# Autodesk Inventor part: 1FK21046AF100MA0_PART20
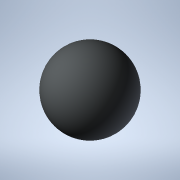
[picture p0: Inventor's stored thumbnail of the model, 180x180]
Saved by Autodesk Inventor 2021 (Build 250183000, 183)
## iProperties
Created: 2025-04
Part Number: 1FK21046AF100MA0_PART20
Material: Generic
Catalog Web Link: www.3dfindit.com
Description: -Servo synchronous motor
Document SubType Name: Modeling
Designer: psAdmin
Mass: 0.137258 g
Surface Area: 1.2868 cm^2
Volume: 0.137258 cm^3
Density: 1 g/cm^3
Appearance: PSOLRGB-212-217-219
Category: PARTsolutions
Title: 1FK21046AF100MA0_PART20
Author: Cadenas PARTsolutions
Comments: Servo synchronous motor
Sending System: PARTsolutions
Preprocessor: ST-DEVELOPER v19.3
PSOL_IDENT_0: {$CADENAS_DATA/23d-libs/siemens_ag/_cat_/4f/2b/1fk21046af100ma0.prj},216 {VTYP=3D},{NB=1FK21046AF100
PSOL_IDENT_1: MA0_PART20},{LINA=1FK21046AF100MA0_PART20},{NN=1FK21046AF100MA0_PART20},{NOPRJ=TRUE},{DATE=19.08.202
PSOL_IDENT_2: 5 14:00:37},{GEOMDATE=30.07.2025 02:01:06},{VERSION=},{LINEID=10},{WBVAR=},{WBNUMERIC=}  {NB=1FK2104
PSOL_IDENT_3: 6AF100MA0_PART20},{LINA=1FK21046AF100MA0_PART20},{KT=DUMMY},{PREVIEW=../../../_pool_/cb/72/p_d211_xx
PSOL_IDENT_4: _00434j.png},{DESCSHORT=SIMOTICS S-1FK2 HD, SINAMICS S210 3AC 400V-480V, 3.2 Nm, 3000 rpm},{DESCLONG=
PSOL_IDENT_5: SIMOTICS S-1FK2 HD servo motor M0=3.2 Nm; PN = 1 kW at nN=3000 rpm (380-480 V); PN = 0.5 kW at nN=15
PSOL_IDENT_6: 00 rpm (200-240 V); with holding brake; degree of protection IP64; cylindrical shaft D19x40mm; absol
PSOL_IDENT_7: ute encoder 22-bit + 12-bit multiturn (encoder AM22DQC); with OCC interface; plug size M17, rotatabl
PSOL_IDENT_8: e; SIMOTICS S-1FK2 servomotorfor a wide range of uses in industrial environments. SIMOTICS S‑1FK2 se
PSOL_IDENT_9: rvomotors are compact synchronous motors with a high dynamic performance that set themselves apart a
PSOL_IDENT_10: s a result of their high power density, degree of protection and overload capability. The motors are
PSOL_IDENT_11: available in two variants: as High Dynamic variant (highest dynamic performance as a result of the
PSOL_IDENT_12: low intrinsic moment of inertia for applications demanding a high dynamic performance with low moved
PSOL_IDENT_13: masses) - and as Compact variant (precise and stable closed-loop control for medium up to large mov
PSOL_IDENT_14: ed masses as a result of a medium intrinsic moment of inertia). SIMOTICSS‑1FK2 servomotors fully exp
PSOL_IDENT_15: loit their strengths in a system with the SINAMICSS210 frequency converter and simple connection usi
PSOL_IDENT_16: ng the one cable connection (OCC). Advantages include the short control and positioning times, fast
PSOL_IDENT_17: and precise correction of disturbing quantities as well as stable control with a high dynamic perfor
PSOL_IDENT_18: mance. The servo motors can be configured to address a wide range of requirements. For example with
PSOL_IDENT_19: and without holding brake, IP64 or IP65 degree of protection, singleturn or multiturn absolute encod
PSOL_IDENT_20: ers - to name just a few. Further, the servomotors are available in different shaft heights extendin
PSOL_IDENT_21: g from 20 to 100. A shaft sealing ring is available to achieve an IP65 degree of protection and for
PSOL_IDENT_22: subsequent mounting at the motor or as spare part. SIMOTICS - the optimum motor for each and every m
PSOL_IDENT_23: otion control application.},{INTNO=195125049673},{SUPPLIERALTNO=1FK2104-6AF10-0MA0},{MANUID=1FK21046
PSOL_IDENT_24: AF100MA0},{MANUNAME=Siemens},{MANUTYPEDESC=Synchronous motor 1FK2-HD 3.2 NM},{AAU732=SIMOTICS},{AAO0
PSOL_IDENT_25: 57=S-1FK2},{AAU734=SIMOTICS S-1FK2 HD servo motor M0=3.2 Nm; PN = 1 kW at nN=3000 rpm (380-480 V); P
PSOL_IDENT_26: N = 0.5 kW at nN=1500 rpm (200-240 V); with holding brake; degree of protection IP64; cylindrical sh
PSOL_IDENT_27: aft D19x40mm; absolute encoder 22-bit + 12-bit multiturn (encoder AM22DQC); with OCC interface; plug
PSOL_IDENT_28: size M17, rotatable;},{AAW338=Synchronous motor 1FK2-HD 3.2 NM},{AAO742=SIMOTICS},{AAO663=404294869
PSOL_IDENT_29: 4534},{NOCUPEROU=1},{PRICEQUANTITY=1},{QUANTITYMIN=1},{QUANTITYINT=1},{CTN=85015220},{COO=DE},{AAO67
PSOL_IDENT_30: 6=1FK2104-6AF10-0MA0},{AAO677=Siemens AG},{ORDERUNIT=C62},{CONTENTUNIT=C62}
NB: 1FK21046AF100MA0_PART20
NT: Servo synchronous motor
NBSYN: $MANUID._PART20
LINA: 1FK21046AF100MA0_PART20
CATALOG: SIEMENS
PREVIEW: ../../../_pool_/cb/72/p_d211_xx_00434j.png
DESCSHORT: SIMOTICS S-1FK2 HD, SINAMICS S210 3AC 400V-480V, 3.2 Nm, 3000 rpm
DESCLONG: SIMOTICS S-1FK2 HD servo motor M0=3.2 Nm; PN = 1 kW at nN=3000 rpm (380-480 V); PN = 0.5 kW at nN=1500 rpm (200-240 V); with holding brake; degree of protection
INTNO: 195125049673
SUPPLIERALTNO: 1FK2104-6AF10-0MA0
MANUID: 1FK21046AF100MA0
MANUNAME: Siemens
MANUTYPEDESC: Synchronous motor 1FK2-HD 3.2 NM
AAU732: SIMOTICS
AAO057: S-1FK2
AAU734: SIMOTICS S-1FK2 HD servo motor M0=3.2 Nm; PN = 1 kW at nN=3000 rpm (380-480 V); PN = 0.5 kW at nN=1500 rpm (200-240 V); with holding brake; degree of protection
AAW338: Synchronous motor 1FK2-HD 3.2 NM
AAO742: SIMOTICS
AAO663: 4042948694534.0
NOCUPEROU: 1
PRICEQUANTITY: 1
QUANTITYMIN: 1
QUANTITYINT: 1
CTN: 85015220
COO: DE
ARTICLENO: 1FK21046AF100MA0_PART20
BOMINFO: 1FK21046AF100MA0_PART20
CREATOR: CADENAS GmbH
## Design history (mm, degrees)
feature "2025_04_17_14_59_39_0177"
body "Solid1"
